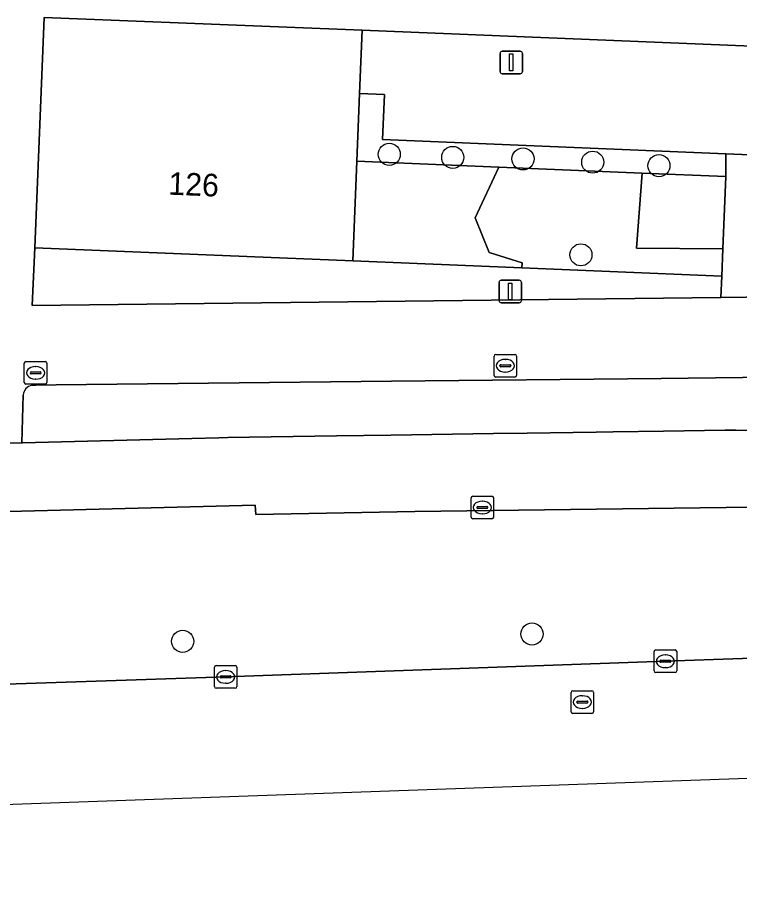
# Model space of a CAD drawing. Extents: x 160888 to 161385, y 386490 to 386908.
# Drawn here: x 161205.21 to 161237.19, y 386494.25 to 386533.16 of the extents above; entities that cross this region are included whole.
import ezdxf

# ---------------------------------------------------------------- set-up
doc = ezdxf.new("R2010")
doc.units = 0
for name, color, linetype in [('IMGEO_Berm_groen', 7, 'Continuous'), ('IMGEO_Boom', 7, 'Continuous'), ('IMGEO_Fietspad_gesloten', 7, 'Continuous'), ('IMGEO_Groenvoorziening', 7, 'Continuous'), ('IMGEO_Haag', 7, 'Continuous'), ('IMGEO_Kolk', 7, 'Continuous'), ('IMGEO_Lichtmast', 7, 'Continuous'), ('IMGEO_Pand', 7, 'Continuous'), ('IMGEO_Pand_nummerreeks', 7, 'Continuous'), ('IMGEO_Parkeervlak_open', 7, 'Continuous'), ('IMGEO_Rijbaan_regionaal_gesloten', 7, 'Continuous'), ('IMGEO_Rioolput', 7, 'Continuous'), ('IMGEO_Voetgangersgebied_open', 7, 'Continuous'), ('IMGEO_Voetpad_open', 7, 'Continuous')]:
    doc.layers.add(name, color=color, linetype=linetype)

msp = doc.modelspace()

# ---------------------------------------------------------------- linework, layer by layer
at = {"layer": 'IMGEO_Berm_groen'}
for points in [[(161313.071, 386509.592), (161311.776, 386509.705), (161311.73, 386509.285), (161306.097, 386509.668), (161267.164, 386511.376), (161259.697, 386511.429), (161237.753, 386511.488), (161222.805, 386511.284), (161215.758, 386511.159), (161215.734, 386511.569), (161167.964, 386510.348), (161127.225, 386509.29)], [(161133.563, 386501.204), (161154.024, 386501.918), (161175.497, 386502.675), (161194.971, 386503.319), (161214.429, 386503.969), (161233.906, 386504.66), (161254.372, 386505.373), (161273.833, 386506.048), (161292.306, 386506.7), (161322.733, 386507.751)]]:
    msp.add_lwpolyline(points, dxfattribs=at)
at = {"layer": 'IMGEO_Boom'}
for centre in [(161221.673, 386527.103), (161224.488, 386526.967), (161227.6, 386526.903), (161230.689, 386526.757), (161233.619, 386526.601), (161230.162, 386522.654), (161227.997, 386505.867), (161212.524, 386505.543)]:
    msp.add_circle(centre, 0.489, dxfattribs=at)
at = {"layer": 'IMGEO_Fietspad_gesloten'}
for points in [[(161267.578, 386514.754), (161262.551, 386514.831), (161253.325, 386514.853), (161253.233, 386514.853), (161244.609, 386514.875), (161237.032, 386514.894), (161236.549, 386514.895), (161233.821, 386514.854), (161231.599, 386514.82), (161230.845, 386514.809), (161227.787, 386514.763), (161226.292, 386514.741), (161221.75, 386514.672), (161219.333, 386514.636), (161214.527, 386514.564), (161214.131, 386514.554), (161212.923, 386514.523), (161205.423, 386514.331), (161205.404, 386514.331), (161197.221, 386514.122)], [(161106.833, 386506.491), (161109.839, 386506.955), (161116.836, 386508.035), (161123.035, 386508.931), (161127.225, 386509.29), (161167.964, 386510.348), (161215.734, 386511.569), (161215.758, 386511.159), (161222.805, 386511.284), (161237.753, 386511.488), (161259.697, 386511.429), (161267.164, 386511.376), (161306.097, 386509.668), (161311.73, 386509.285), (161311.776, 386509.705), (161313.071, 386509.592)]]:
    msp.add_lwpolyline(points, dxfattribs=at)
at = {"layer": 'IMGEO_Groenvoorziening'}
for points in [[(161236.579, 386526.123), (161236.584, 386527.124), (161221.376, 386527.753), (161221.46, 386529.753), (161220.36, 386529.791), (161220.241, 386526.799), (161226.532, 386526.539), (161232.876, 386526.277)], [(161226.532, 386526.539), (161220.241, 386526.799), (161220.066, 386522.389), (161227.542, 386522.081), (161227.556, 386522.301), (161226.101, 386522.756), (161225.477, 386524.293)], [(161232.876, 386526.277), (161226.532, 386526.539), (161225.477, 386524.293), (161226.101, 386522.756), (161227.556, 386522.301), (161227.542, 386522.081), (161236.404, 386521.716), (161236.452, 386522.922), (161232.632, 386522.951)], [(161236.579, 386526.123), (161232.876, 386526.277), (161232.632, 386522.951), (161236.452, 386522.922)], [(161227.542, 386522.081), (161220.066, 386522.389), (161205.979, 386522.969), (161205.859, 386520.404), (161227.455, 386520.659), (161236.366, 386520.764), (161236.404, 386521.716)]]:
    msp.add_lwpolyline(points, close=True, dxfattribs=at)
for points in [[(161252.863, 386517.39), (161252.478, 386517.39), (161239.735, 386517.251), (161233.722, 386517.186), (161221.767, 386517.056), (161206.921, 386516.896), (161206.016, 386516.884), (161205.917, 386516.886), (161205.844, 386516.883)], [(161205.404, 386514.331), (161205.423, 386514.331), (161212.923, 386514.523), (161214.131, 386514.554), (161214.527, 386514.564), (161219.333, 386514.636), (161221.75, 386514.672), (161226.292, 386514.741), (161227.787, 386514.763), (161230.845, 386514.809), (161231.599, 386514.82), (161233.821, 386514.854), (161236.549, 386514.895), (161237.032, 386514.894), (161244.609, 386514.875), (161253.233, 386514.853), (161253.313, 386516.825)], [(161205.457, 386516.449), (161205.404, 386514.331)]]:
    msp.add_lwpolyline(points, dxfattribs=at)
msp.add_arc((161205.938, 386516.409), 0.483, 101.2631, 175.2898, dxfattribs=at)
at = {"layer": 'IMGEO_Haag'}
msp.add_lwpolyline([(161236.579, 386526.123), (161236.584, 386527.124), (161221.376, 386527.753), (161221.46, 386529.753), (161220.36, 386529.791), (161220.241, 386526.799), (161226.532, 386526.539), (161232.876, 386526.277)], close=True, dxfattribs=at)
at = {"layer": 'IMGEO_Kolk'}
for p, q in [((161205.583, 386517.929), (161206.435, 386517.929)), ((161226.315, 386517.318), (161226.315, 386518.17)), ((161226.39, 386518.244), (161227.242, 386518.244)), ((161226.803, 386518.024), (161226.828, 386518.024)), ((161227.316, 386518.17), (161227.316, 386517.318)), ((161205.508, 386517.003), (161205.508, 386517.855)), ((161205.996, 386517.709), (161206.021, 386517.709)), ((161206.509, 386517.855), (161206.509, 386517.003)), ((161226.574, 386517.738), (161226.574, 386517.75)), ((161227.012, 386517.701), (161226.614, 386517.701)), ((161226.617, 386517.787), (161227.015, 386517.787)), ((161227.058, 386517.75), (161227.058, 386517.738)), ((161205.767, 386517.423), (161205.767, 386517.435)), ((161206.205, 386517.386), (161205.807, 386517.386)), ((161205.81, 386517.472), (161206.208, 386517.472)), ((161206.019, 386517.149), (161205.994, 386517.149)), ((161206.251, 386517.435), (161206.251, 386517.423)), ((161227.242, 386517.244), (161226.39, 386517.244)), ((161226.826, 386517.464), (161226.801, 386517.464)), ((161206.435, 386516.929), (161205.583, 386516.929)), ((161225.298, 386511.042), (161225.298, 386511.894)), ((161225.373, 386511.968), (161226.225, 386511.968)), ((161225.786, 386511.748), (161225.811, 386511.748)), ((161226.299, 386511.894), (161226.299, 386511.042)), ((161225.557, 386511.462), (161225.557, 386511.474)), ((161225.995, 386511.425), (161225.597, 386511.425)), ((161225.6, 386511.511), (161225.998, 386511.511)), ((161226.041, 386511.474), (161226.041, 386511.462)), ((161226.225, 386510.968), (161225.373, 386510.968)), ((161225.809, 386511.188), (161225.784, 386511.188)), ((161233.405, 386504.234), (161233.405, 386505.086)), ((161233.48, 386505.16), (161234.332, 386505.16)), ((161234.406, 386505.086), (161234.406, 386504.234)), ((161233.707, 386504.703), (161234.105, 386504.703)), ((161233.893, 386504.94), (161233.918, 386504.94)), ((161213.928, 386503.543), (161213.928, 386504.395)), ((161214.003, 386504.469), (161214.855, 386504.469)), ((161214.929, 386504.395), (161214.929, 386503.543)), ((161233.664, 386504.654), (161233.664, 386504.666)), ((161234.102, 386504.617), (161233.704, 386504.617)), ((161233.916, 386504.38), (161233.891, 386504.38)), ((161234.148, 386504.666), (161234.148, 386504.654)), ((161214.187, 386503.963), (161214.187, 386503.975)), ((161214.625, 386503.926), (161214.227, 386503.926)), ((161214.23, 386504.012), (161214.628, 386504.012)), ((161214.416, 386504.249), (161214.441, 386504.249)), ((161214.671, 386503.975), (161214.671, 386503.963)), ((161234.332, 386504.16), (161233.48, 386504.16)), ((161214.439, 386503.689), (161214.414, 386503.689)), ((161214.855, 386503.469), (161214.003, 386503.469))]:
    msp.add_line(p, q, dxfattribs=at)
for points in [[(161205.583, 386517.929), (161206.435, 386517.929)], [(161226.315, 386517.318), (161226.315, 386518.17)], [(161226.39, 386518.244), (161227.242, 386518.244)], [(161227.316, 386518.17), (161227.316, 386517.318)], [(161205.508, 386517.003), (161205.508, 386517.855)], [(161206.509, 386517.855), (161206.509, 386517.003)], [(161227.242, 386517.244), (161226.39, 386517.244)], [(161206.435, 386516.929), (161205.583, 386516.929)], [(161225.298, 386511.042), (161225.298, 386511.894)], [(161225.373, 386511.968), (161226.225, 386511.968)], [(161226.299, 386511.894), (161226.299, 386511.042)], [(161226.225, 386510.968), (161225.373, 386510.968)], [(161233.405, 386504.234), (161233.405, 386505.086)], [(161233.48, 386505.16), (161234.332, 386505.16)], [(161234.406, 386505.086), (161234.406, 386504.234)], [(161213.928, 386503.543), (161213.928, 386504.395)], [(161214.003, 386504.469), (161214.855, 386504.469)], [(161214.929, 386504.395), (161214.929, 386503.543)], [(161234.332, 386504.16), (161233.48, 386504.16)], [(161214.855, 386503.469), (161214.003, 386503.469)]]:
    msp.add_lwpolyline(points, dxfattribs=at)
for centre, radius, start, end in [((161205.585, 386517.853), 0.0765, 91.552, 178.448), ((161205.585, 386517.853), 0.0765, 91.552, 178.448), ((161206.433, 386517.853), 0.0765, 1.552, 88.448), ((161206.433, 386517.853), 0.0765, 1.552, 88.448), ((161226.392, 386518.168), 0.0765, 91.552, 178.448), ((161226.392, 386518.168), 0.0765, 91.552, 178.448), ((161227.24, 386518.168), 0.0765, 1.552, 88.448), ((161227.24, 386518.168), 0.0765, 1.552, 88.448), ((161226.614, 386517.747), 0.0403, 85.8775, 175.7526), ((161226.611, 386517.737), 0.0366, 178.938, 274.7102), ((161227.015, 386517.744), 0.043, 264.8664, 352.4533), ((161227.019, 386517.749), 0.0386, 1.7309, 96.639), ((161205.807, 386517.432), 0.0403, 85.8775, 175.7526), ((161205.804, 386517.422), 0.0366, 178.938, 274.7102), ((161206.208, 386517.429), 0.043, 264.8664, 352.4533), ((161206.212, 386517.434), 0.0386, 1.7309, 96.639), ((161226.392, 386517.32), 0.0765, 181.552, 268.448), ((161226.392, 386517.32), 0.0765, 181.552, 268.448), ((161227.24, 386517.32), 0.0765, 271.552, 358.448), ((161227.24, 386517.32), 0.0765, 271.552, 358.448), ((161205.585, 386517.005), 0.0765, 181.552, 268.448), ((161205.585, 386517.005), 0.0765, 181.552, 268.448), ((161206.433, 386517.005), 0.0765, 271.552, 358.448), ((161206.433, 386517.005), 0.0765, 271.552, 358.448), ((161225.375, 386511.892), 0.0765, 91.552, 178.448), ((161225.375, 386511.892), 0.0765, 91.552, 178.448), ((161226.223, 386511.892), 0.0765, 1.552, 88.448), ((161226.223, 386511.892), 0.0765, 1.552, 88.448), ((161225.597, 386511.471), 0.0403, 85.8775, 175.7526), ((161225.594, 386511.461), 0.0366, 178.938, 274.7102), ((161225.998, 386511.468), 0.043, 264.8664, 352.4533), ((161226.002, 386511.473), 0.0386, 1.7309, 96.639), ((161225.375, 386511.044), 0.0765, 181.552, 268.448), ((161225.375, 386511.044), 0.0765, 181.552, 268.448), ((161226.223, 386511.044), 0.0765, 271.552, 358.448), ((161226.223, 386511.044), 0.0765, 271.552, 358.448), ((161233.482, 386505.084), 0.0765, 91.552, 178.448), ((161233.482, 386505.084), 0.0765, 91.552, 178.448), ((161234.33, 386505.084), 0.0765, 1.552, 88.448), ((161234.33, 386505.084), 0.0765, 1.552, 88.448), ((161233.704, 386504.663), 0.0403, 85.8775, 175.7526), ((161234.109, 386504.665), 0.0386, 1.7309, 96.639), ((161214.005, 386504.393), 0.0765, 91.552, 178.448), ((161214.005, 386504.393), 0.0765, 91.552, 178.448), ((161214.853, 386504.393), 0.0765, 1.552, 88.448), ((161214.853, 386504.393), 0.0765, 1.552, 88.448), ((161233.701, 386504.653), 0.0366, 178.938, 274.7102), ((161234.105, 386504.66), 0.043, 264.8664, 352.4533), ((161214.227, 386503.972), 0.0403, 85.8775, 175.7526), ((161214.224, 386503.962), 0.0366, 178.938, 274.7102), ((161214.628, 386503.969), 0.043, 264.8664, 352.4533), ((161214.632, 386503.974), 0.0386, 1.7309, 96.639), ((161233.482, 386504.236), 0.0765, 181.552, 268.448), ((161233.482, 386504.236), 0.0765, 181.552, 268.448), ((161234.33, 386504.236), 0.0765, 271.552, 358.448), ((161234.33, 386504.236), 0.0765, 271.552, 358.448), ((161214.005, 386503.545), 0.0765, 181.552, 268.448), ((161214.005, 386503.545), 0.0765, 181.552, 268.448), ((161214.853, 386503.545), 0.0765, 271.552, 358.448), ((161214.853, 386503.545), 0.0765, 271.552, 358.448)]:
    msp.add_arc(centre, radius, start, end, dxfattribs=at)
for centre, major_axis, ratio, start_param, end_param in [((161226.802, 386517.744), (-0.387, 0.002), 0.722429, 4.712389, 7.853982), ((161226.827, 386517.744), (-0.39, 0.002), 0.717154, 1.570796, 4.712389), ((161205.995, 386517.429), (-0.387, 0.002), 0.722429, 4.712389, 7.853982), ((161206.02, 386517.429), (-0.39, 0.002), 0.717154, 1.570796, 4.712389), ((161225.785, 386511.468), (-0.387, 0.002), 0.722429, 4.712389, 7.853982), ((161225.81, 386511.468), (-0.39, 0.002), 0.717154, 1.570796, 4.712389), ((161233.892, 386504.66), (-0.387, 0.002), 0.722429, 4.712389, 7.853982), ((161233.917, 386504.66), (-0.39, 0.002), 0.717154, 1.570796, 4.712389), ((161214.415, 386503.969), (-0.387, 0.002), 0.722429, 4.712389, 7.853982), ((161214.44, 386503.969), (-0.39, 0.002), 0.717154, 1.570796, 4.712389)]:
    msp.add_ellipse(centre, major_axis=major_axis, ratio=ratio, start_param=start_param, end_param=end_param, dxfattribs=at)
at = {"layer": 'IMGEO_Lichtmast'}
for p, q in [((161226.581, 386530.771), (161226.581, 386531.571)), ((161226.581, 386531.571), (161226.581, 386530.771)), ((161226.681, 386531.671), (161227.471, 386531.671)), ((161227.471, 386531.671), (161226.681, 386531.671)), ((161227.571, 386531.571), (161227.571, 386530.771)), ((161227.571, 386530.771), (161227.571, 386531.571)), ((161227.471, 386530.671), (161226.681, 386530.671)), ((161226.681, 386530.671), (161227.471, 386530.671)), ((161226.537, 386520.631), (161226.537, 386521.431)), ((161226.537, 386521.431), (161226.537, 386520.631)), ((161226.637, 386521.531), (161227.427, 386521.531)), ((161227.427, 386521.531), (161226.637, 386521.531)), ((161227.527, 386521.431), (161227.527, 386520.631)), ((161227.527, 386520.631), (161227.527, 386521.431)), ((161227.427, 386520.531), (161226.637, 386520.531)), ((161226.637, 386520.531), (161227.427, 386520.531))]:
    msp.add_line(p, q, dxfattribs=at)
for points in [[(161227.001, 386531.546), (161227.151, 386531.546), (161227.151, 386530.796), (161227.001, 386530.796), (161227.001, 386531.546)], [(161226.957, 386521.406), (161227.107, 386521.406), (161227.107, 386520.656), (161226.957, 386520.656), (161226.957, 386521.406)]]:
    msp.add_lwpolyline(points, dxfattribs=at)
for centre, start, end in [((161226.681, 386531.571), 90, 180), ((161226.681, 386531.571), 90, 180), ((161227.471, 386531.571), 0, 90), ((161227.471, 386531.571), 360, 90), ((161226.681, 386530.771), 180, 270), ((161226.681, 386530.771), 180, 270), ((161227.471, 386530.771), 270, 0), ((161227.471, 386530.771), 270, 0), ((161226.637, 386521.431), 90, 180), ((161226.637, 386521.431), 90, 180), ((161227.427, 386521.431), 0, 90), ((161227.427, 386521.431), 360, 90), ((161226.637, 386520.631), 180, 270), ((161226.637, 386520.631), 180, 270), ((161227.427, 386520.631), 270, 0), ((161227.427, 386520.631), 270, 0)]:
    msp.add_arc(centre, 0.1, start, end, dxfattribs=at)
at = {"layer": 'IMGEO_Pand'}
msp.add_lwpolyline([(161220.471, 386532.599), (161206.385, 386533.158), (161205.979, 386522.969), (161220.066, 386522.389), (161220.241, 386526.799), (161220.36, 386529.791)], close=True, dxfattribs=at)
at = {"layer": 'IMGEO_Parkeervlak_open'}
msp.add_lwpolyline([(161253.921, 386531.225), (161220.471, 386532.599), (161220.36, 386529.791), (161221.46, 386529.753), (161221.376, 386527.753), (161236.584, 386527.124), (161253.58, 386526.42), (161253.732, 386526.414)], close=True, dxfattribs=at)
at = {"layer": 'IMGEO_Rijbaan_regionaal_gesloten'}
msp.add_lwpolyline([(161083.554, 386494.25), (161197.468, 386498.064), (161264.673, 386500.448), (161323.284, 386502.509), (161323.08, 386507.769), (161322.733, 386507.751), (161292.306, 386506.7), (161273.833, 386506.048), (161254.372, 386505.373), (161233.906, 386504.66), (161214.429, 386503.969), (161194.971, 386503.319), (161175.497, 386502.675), (161154.024, 386501.918), (161133.563, 386501.204)], dxfattribs=at)
at = {"layer": 'IMGEO_Rioolput'}
for p, q in [((161229.727, 386502.427), (161229.727, 386503.279)), ((161229.802, 386503.353), (161230.654, 386503.353)), ((161230.215, 386503.133), (161230.24, 386503.133)), ((161230.728, 386503.279), (161230.728, 386502.427)), ((161229.986, 386502.847), (161229.986, 386502.859)), ((161230.424, 386502.81), (161230.026, 386502.81)), ((161230.029, 386502.896), (161230.427, 386502.896)), ((161230.47, 386502.859), (161230.47, 386502.847)), ((161230.654, 386502.353), (161229.802, 386502.353)), ((161230.238, 386502.573), (161230.213, 386502.573))]:
    msp.add_line(p, q, dxfattribs=at)
for points in [[(161229.727, 386502.427), (161229.727, 386503.279)], [(161229.802, 386503.353), (161230.654, 386503.353)], [(161230.728, 386503.279), (161230.728, 386502.427)], [(161230.654, 386502.353), (161229.802, 386502.353)]]:
    msp.add_lwpolyline(points, dxfattribs=at)
for centre, radius, start, end in [((161229.804, 386503.277), 0.0765, 91.552, 178.448), ((161229.804, 386503.277), 0.0765, 91.552, 178.448), ((161230.652, 386503.277), 0.0765, 1.552, 88.448), ((161230.652, 386503.277), 0.0765, 1.552, 88.448), ((161230.026, 386502.856), 0.0403, 85.8775, 175.7526), ((161230.023, 386502.846), 0.0366, 178.938, 274.7102), ((161230.427, 386502.853), 0.043, 264.8664, 352.4533), ((161230.431, 386502.858), 0.0386, 1.7309, 96.639), ((161229.804, 386502.429), 0.0765, 181.552, 268.448), ((161229.804, 386502.429), 0.0765, 181.552, 268.448), ((161230.652, 386502.429), 0.0765, 271.552, 358.448), ((161230.652, 386502.429), 0.0765, 271.552, 358.448)]:
    msp.add_arc(centre, radius, start, end, dxfattribs=at)
for centre, major_axis, ratio, start_param, end_param in [((161230.214, 386502.853), (-0.387, 0.002), 0.722429, 4.712389, 7.853982), ((161230.239, 386502.853), (-0.39, 0.002), 0.717154, 1.570796, 4.712389)]:
    msp.add_ellipse(centre, major_axis=major_axis, ratio=ratio, start_param=start_param, end_param=end_param, dxfattribs=at)
at = {"layer": 'IMGEO_Voetgangersgebied_open'}
msp.add_lwpolyline([(161253.921, 386531.225), (161253.732, 386526.414), (161253.58, 386526.42), (161253.549, 386525.76), (161253.343, 386521.315), (161238.627, 386521.923), (161238.58, 386520.79), (161237.489, 386520.777), (161236.366, 386520.764), (161227.455, 386520.659), (161205.859, 386520.404), (161205.979, 386522.969), (161206.385, 386533.158), (161220.471, 386532.599)], close=True, dxfattribs=at)
for points in [[(161205.844, 386516.883), (161205.917, 386516.886), (161206.016, 386516.884), (161206.921, 386516.896), (161221.767, 386517.056), (161233.722, 386517.186), (161239.735, 386517.251), (161252.478, 386517.39), (161252.863, 386517.39)], [(161197.175, 386516.465), (161197.188, 386516.423), (161197.194, 386516.396), (161197.201, 386516.355), (161197.204, 386516.312), (161197.205, 386516.146), (161197.209, 386515.225), (161197.21, 386514.917), (161197.221, 386514.122), (161205.404, 386514.331), (161205.457, 386516.449)]]:
    msp.add_lwpolyline(points, dxfattribs=at)
msp.add_arc((161205.938, 386516.409), 0.483, 101.2631, 175.2898, dxfattribs=at)
at = {"layer": 'IMGEO_Voetpad_open'}
msp.add_lwpolyline([(161253.58, 386526.42), (161236.584, 386527.124), (161236.579, 386526.123), (161236.452, 386522.922), (161236.404, 386521.716), (161236.366, 386520.764), (161237.489, 386520.777), (161238.58, 386520.79), (161238.627, 386521.923), (161238.527, 386521.927), (161238.531, 386522.021), (161238.703, 386526.033), (161238.718, 386526.371), (161253.549, 386525.76)], close=True, dxfattribs=at)

# ---------------------------------------------------------------- texts
at = {"layer": 'IMGEO_Pand_nummerreeks'}
msp.add_text('126', height=1, rotation=357.6671, dxfattribs=at).set_placement((161211.878, 386525.32))

doc.saveas('drawing.dxf')
